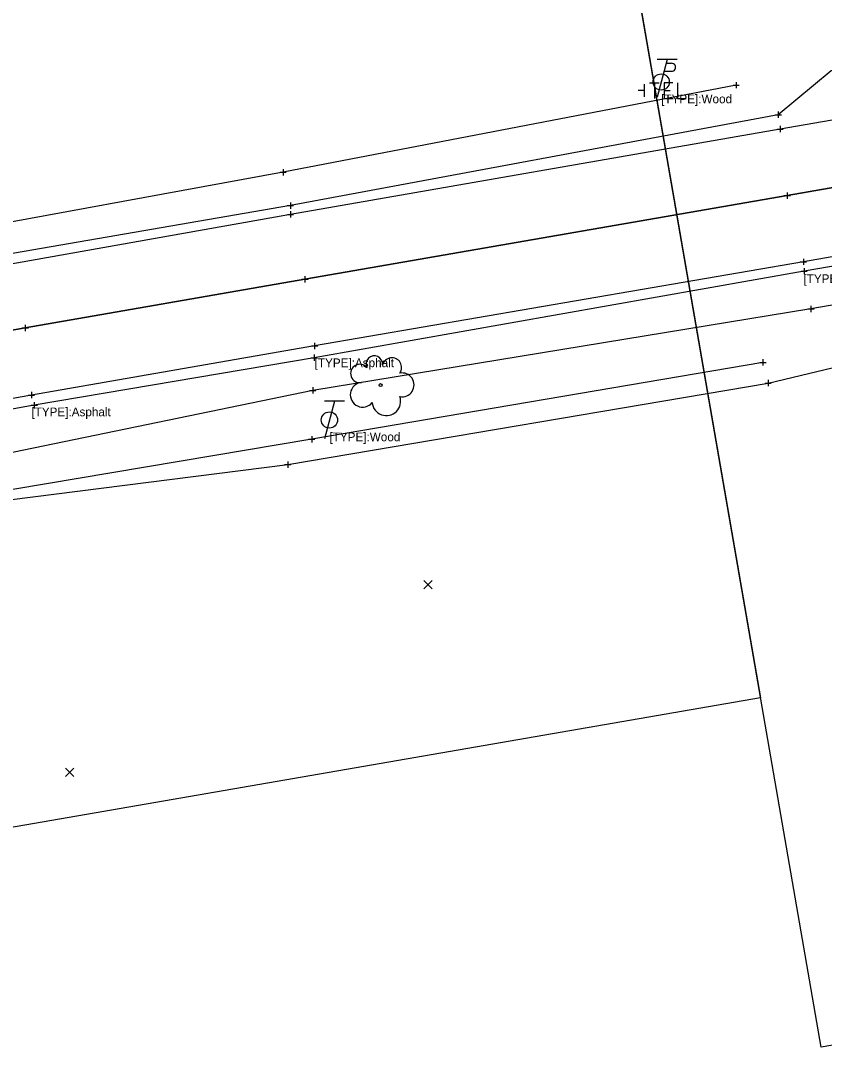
# Model space of a CAD drawing. Extents: x 1386013 to 1389776, y 604170 to 607009.
# Drawn here: x 1388604.6 to 1388733.1, y 604901.9 to 605068.3 of the extents above; entities that cross this region are included whole.
import ezdxf

# ---------------------------------------------------------------- set-up
doc = ezdxf.new("R2010")
doc.units = 0
for name, color, linetype in [('_CIVIL_CONSTRUCTION', 7, 'Continuous'), ('DV_X_Text', 7, 'Continuous'), ('PM_X_CL_Double_Solid', 7, 'Continuous'), ('PV_X_COP', 7, 'Continuous'), ('PV_X_EOP', 7, 'Continuous'), ('PV_X_Shoulder', 7, 'Continuous'), ('RD_X_Fence', 7, 'Continuous'), ('SH_Cut_Line', 7, 'Continuous'), ('SV_P_Mon_Cells_Set', 7, 'Continuous'), ('SV_X_Random_Point', 7, 'Continuous'), ('SV_X_Text', 7, 'Continuous'), ('SV_X_Toe_of_Slope', 7, 'Continuous'), ('SV_X_Top_of_Bank', 7, 'Continuous'), ('UT_X_Telecom_Cells', 7, 'Continuous')]:
    doc.layers.add(name, color=color, linetype=linetype)

msp = doc.modelspace()

# ---------------------------------------------------------------- linework, layer by layer
at = {"layer": '_CIVIL_CONSTRUCTION'}
msp.add_circle((1388662.13, 605010.01), 0.24, dxfattribs=at)
for centre, radius, start, end in [((1388661.14, 605013.38), 1.32, 354.0047, 205.9741), ((1388663.95, 605012.84), 1.55, 323.83, 165.0376), ((1388658.82, 605011.88), 1.47, 39.0625, 279.5412), ((1388665.59, 605010.05), 1.91, 259.1453, 101.4596), ((1388659.27, 605008.47), 1.97, 96.1722, 320.5737), ((1388663.07, 605007.41), 2.28, 184.9476, 19.4572)]:
    msp.add_arc(centre, radius, start, end, dxfattribs=at)
at = {"layer": 'DV_X_Text'}
for p, q in [((1388718.53, 605058.04), (1388719.53, 605058.04)), ((1388719.03, 605058.54), (1388719.03, 605057.54)), ((1388719.03, 605058.04), (1388719.03, 605058.04)), ((1388725.28, 605053.3), (1388726.28, 605053.3)), ((1388725.78, 605053.8), (1388725.78, 605052.8)), ((1388725.78, 605053.3), (1388725.78, 605053.3)), ((1388725.58, 605051), (1388726.58, 605051)), ((1388726.08, 605051.5), (1388726.08, 605050.5)), ((1388726.08, 605051), (1388726.08, 605051)), ((1388646.05, 605044.09), (1388647.05, 605044.09)), ((1388646.55, 605044.59), (1388646.55, 605043.59)), ((1388646.55, 605044.09), (1388646.55, 605044.09)), ((1388727.22, 605040.85), (1388727.22, 605039.85)), ((1388647.71, 605039.25), (1388647.71, 605038.25)), ((1388726.72, 605040.35), (1388727.72, 605040.35)), ((1388727.22, 605040.35), (1388727.22, 605040.35)), ((1388647.21, 605038.75), (1388648.21, 605038.75)), ((1388647.23, 605037.35), (1388648.23, 605037.35)), ((1388647.71, 605038.75), (1388647.71, 605038.75)), ((1388647.73, 605037.85), (1388647.73, 605036.85)), ((1388647.73, 605037.35), (1388647.73, 605037.35)), ((1388729.3, 605029.75), (1388730.3, 605029.75)), ((1388729.8, 605030.25), (1388729.8, 605029.25)), ((1388729.8, 605029.75), (1388729.8, 605029.75)), ((1388650.04, 605027.46), (1388650.04, 605026.46)), ((1388729.42, 605028.26), (1388730.42, 605028.26)), ((1388729.92, 605028.76), (1388729.92, 605027.76)), ((1388729.92, 605028.26), (1388729.92, 605028.26)), ((1388649.54, 605026.96), (1388650.54, 605026.96)), ((1388650.04, 605026.96), (1388650.04, 605026.96)), ((1388730.99, 605022.72), (1388730.99, 605021.72)), ((1388730.49, 605022.22), (1388731.49, 605022.22)), ((1388730.99, 605022.22), (1388730.99, 605022.22)), ((1388604.78, 605019.17), (1388605.78, 605019.17)), ((1388605.28, 605019.67), (1388605.28, 605018.67)), ((1388605.28, 605019.17), (1388605.28, 605019.17)), ((1388651.09, 605016.29), (1388652.09, 605016.29)), ((1388651.59, 605016.79), (1388651.59, 605015.79)), ((1388651.59, 605016.29), (1388651.59, 605016.29)), ((1388651.01, 605014.41), (1388652.01, 605014.41)), ((1388651.51, 605014.91), (1388651.51, 605013.91)), ((1388651.51, 605014.41), (1388651.51, 605014.41)), ((1388723.32, 605014.15), (1388723.32, 605013.15)), ((1388722.82, 605013.65), (1388723.82, 605013.65)), ((1388723.32, 605013.65), (1388723.32, 605013.65)), ((1388724.16, 605010.84), (1388724.16, 605009.84)), ((1388650.79, 605009.18), (1388651.79, 605009.18)), ((1388651.29, 605009.68), (1388651.29, 605008.68)), ((1388651.29, 605009.18), (1388651.29, 605009.18)), ((1388723.66, 605010.34), (1388724.66, 605010.34)), ((1388724.16, 605010.34), (1388724.16, 605010.34)), ((1388605.77, 605008.43), (1388606.77, 605008.43)), ((1388606.27, 605008.93), (1388606.27, 605007.93)), ((1388606.27, 605008.43), (1388606.27, 605008.43)), ((1388606.72, 605007.29), (1388606.72, 605006.29)), ((1388606.22, 605006.79), (1388607.22, 605006.79)), ((1388606.72, 605006.79), (1388606.72, 605006.79)), ((1388650.62, 605001.34), (1388651.62, 605001.34)), ((1388651.12, 605001.84), (1388651.12, 605000.84)), ((1388651.12, 605001.34), (1388651.12, 605001.34)), ((1388646.79, 604997.3), (1388647.79, 604997.3)), ((1388647.29, 604997.8), (1388647.29, 604996.8)), ((1388647.29, 604997.3), (1388647.29, 604997.3))]:
    msp.add_line(p, q, dxfattribs=at)
at = {"layer": 'PM_X_CL_Double_Solid'}
msp.add_lwpolyline([(1387998.85, 604914.97), (1388072.27, 604927.44), (1388150.34, 604940.54), (1388219.83, 604952.56), (1388327.21, 604971.05), (1388378.93, 604979.71), (1388451.75, 604991.99), (1388527.19, 605005.2), (1388605.28, 605019.17), (1388650.04, 605026.96), (1388727.22, 605040.35), (1388785.55, 605050.58), (1388850.55, 605062.12), (1388924.49, 605075.02), (1388990.9, 605086.8), (1389068.68, 605100.88), (1389141.9, 605114.3), (1389207.53, 605126.39), (1389280.37, 605139.49)], dxfattribs=at)
at = {"layer": 'PV_X_COP'}
msp.add_lwpolyline([(1389280.37, 605139.49), (1389207.53, 605126.39), (1389141.9, 605114.3), (1389068.68, 605100.88), (1388990.9, 605086.8), (1388924.49, 605075.02), (1388850.55, 605062.12), (1388785.55, 605050.58), (1388727.22, 605040.35), (1388650.04, 605026.96), (1388605.28, 605019.17), (1388527.19, 605005.2), (1388451.75, 604991.99), (1388378.93, 604979.71), (1388327.21, 604971.05), (1388219.83, 604952.56), (1388150.34, 604940.54), (1388072.27, 604927.44), (1387998.85, 604914.97)], dxfattribs=at)
at = {"layer": 'PV_X_EOP'}
for points in [[(1389278.61, 605149.89), (1389205.62, 605136.54), (1389139.99, 605124.61), (1389067.04, 605111.39), (1388989.39, 605097.25), (1388922.83, 605085.43), (1388849.86, 605072.55), (1388784.25, 605061.08), (1388726.08, 605051), (1388647.73, 605037.35), (1388603.87, 605029.52), (1388525.26, 605015.57), (1388450.62, 605002.62), (1388377.29, 604990.08), (1388325.54, 604981.41), (1388218.94, 604963.01), (1388149.68, 604951.27), (1388070.9, 604937.92), (1387997.67, 604925.46)], [(1389281.27, 605129.06), (1389208.5, 605115.45), (1389143.42, 605103.48), (1389070.14, 605089.92), (1388993.29, 605076.1), (1388925.01, 605063.95), (1388851.7, 605051.17), (1388786.31, 605039.62), (1388729.8, 605029.75), (1388651.59, 605016.29), (1388606.27, 605008.43), (1388528.77, 604994.59), (1388453.6, 604981.36), (1388380.25, 604968.93), (1388328.49, 604960.28), (1388221.37, 604941.87), (1388151.14, 604929.78), (1388073.48, 604916.74), (1388000.2, 604904.18)]]:
    msp.add_lwpolyline(points, dxfattribs=at)
at = {"layer": 'PV_X_Shoulder'}
for points in [[(1389278.32, 605151.38), (1389205.26, 605138.27), (1389139.52, 605126.2), (1389066.77, 605113.2), (1388989.16, 605098.99), (1388922.81, 605087.13), (1388849.4, 605074.38), (1388802.29, 605066.59), (1388793.59, 605066.34), (1388786.16, 605070.01), (1388734.23, 605060.31), (1388725.78, 605053.3), (1388647.71, 605038.75), (1388603.54, 605031.12), (1388524.83, 605017.38), (1388449.88, 605004.12), (1388377.38, 604991.89), (1388326.15, 604983.28), (1388218.46, 604964.95), (1388149.62, 604953.16), (1388070.88, 604939.75), (1387997.08, 604927.24)], [(1389070.3, 605088.44), (1388993.76, 605074.51), (1388925.14, 605062.29), (1388851.88, 605049.71), (1388786.62, 605037.96), (1388729.92, 605028.26), (1388651.51, 605014.41), (1388606.72, 605006.79), (1388529.08, 604992.77), (1388453.76, 604979.45), (1388380.57, 604967.56), (1388328.47, 604958.58), (1388293.07, 604951.05), (1388291.51, 604952.1), (1388221.65, 604940.36), (1388151.37, 604928.17), (1388118.45, 604921.92), (1388113.87, 604918.91), (1388113.3, 604917.2), (1388092.34, 604913.82), (1388086.61, 604916.75), (1388073.66, 604915.38), (1388000.63, 604902.69)]]:
    msp.add_lwpolyline(points, dxfattribs=at)
at = {"layer": 'RD_X_Fence'}
msp.add_lwpolyline([(1388723.32, 605013.65), (1388651.12, 605001.34), (1388603.31, 604993.33), (1388573.84, 604989.92)], dxfattribs=at)
at = {"layer": 'SH_Cut_Line'}
for points in [[(1388732.63, 604904.03), (1388695.08, 605120.8), (1389030.09, 605178.83), (1389067.64, 604962.06)], [(1388387.93, 604901.94), (1388350.38, 605118.71), (1388685.39, 605176.74), (1388722.94, 604959.97)]]:
    msp.add_lwpolyline(points, close=True, dxfattribs=at)
at = {"layer": 'SV_P_Mon_Cells_Set'}
for p, q in [((1388708, 605062.14), (1388706.39, 605056.14)), ((1388709.6, 605062.14), (1388706.4, 605062.14)), ((1388707.84, 605061.54), (1388708.69, 605061.54)), ((1388707.5, 605060.27), (1388708.69, 605060.27))]:
    msp.add_line(p, q, dxfattribs=at)
msp.add_circle((1388707.04, 605058.54), 1.3, dxfattribs=at)
msp.add_arc((1388708.7, 605060.91), 0.638, 268.8767, 91.1233, dxfattribs=at)
at = {"layer": 'SV_X_Random_Point'}
for p, q in [((1388669.06, 604977.41), (1388670.39, 604978.75)), ((1388669.06, 604978.75), (1388670.39, 604977.41)), ((1388611.73, 604947.36), (1388613.06, 604948.7)), ((1388611.73, 604948.7), (1388613.06, 604947.36))]:
    msp.add_line(p, q, dxfattribs=at)
at = {"layer": 'SV_X_Toe_of_Slope'}
for points in [[(1388981.6, 605067.69), (1388926.16, 605057.23), (1388852.38, 605043.81), (1388787.46, 605032), (1388730.99, 605022.22), (1388651.29, 605009.18), (1388603.25, 604999.21), (1388564.46, 604991.1)], [(1388719.03, 605058.04), (1388646.55, 605044.09), (1388589.51, 605033.66), (1388556.39, 605031.64)]]:
    msp.add_lwpolyline(points, dxfattribs=at)
at = {"layer": 'SV_X_Top_of_Bank'}
msp.add_lwpolyline([(1388562.07, 604985.53), (1388598.86, 604991.18), (1388647.29, 604997.3), (1388724.16, 605010.34), (1388772.21, 605021.87), (1388814.77, 605030.03), (1388888.92, 605043.48), (1388966.26, 605059.04), (1388983.11, 605062.53)], dxfattribs=at)
at = {"layer": 'UT_X_Telecom_Cells'}
for p, q in [((1388704.36, 605056.18), (1388704.36, 605058.18)), ((1388704.36, 605057.18), (1388703.37, 605057.18)), ((1388654.76, 605007.43), (1388653.15, 605001.43)), ((1388656.36, 605007.43), (1388653.16, 605007.43))]:
    msp.add_line(p, q, dxfattribs=at)
for points in [[(1388705.18, 605058.42), (1388706.74, 605058.42)], [(1388705.97, 605058.42), (1388705.97, 605055.92)], [(1388708.88, 605058.42), (1388707.52, 605058.42), (1388707.52, 605055.92), (1388708.98, 605055.92)], [(1388709.67, 605058.42), (1388709.67, 605055.92), (1388711.03, 605055.92)], [(1388707.52, 605057.18), (1388708.49, 605057.18)]]:
    msp.add_lwpolyline(points, dxfattribs=at)
msp.add_circle((1388653.96, 605004.43), 1.3, dxfattribs=at)

# ---------------------------------------------------------------- texts
at = {"layer": 'SV_X_Text'}
for s, p in [('[TYPE]:Wood', (1388707.04, 605055.14)), ('[TYPE]:Asphalt', (1388729.8, 605026.35)), ('[TYPE]:Asphalt', (1388651.59, 605012.89)), ('[TYPE]:Asphalt', (1388606.27, 605005.03)), ('[TYPE]:Wood', (1388653.96, 605001.03))]:
    msp.add_text(s, height=1.4, dxfattribs=at).set_placement(p)

doc.saveas('drawing.dxf')
